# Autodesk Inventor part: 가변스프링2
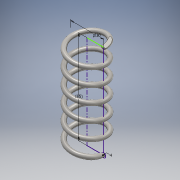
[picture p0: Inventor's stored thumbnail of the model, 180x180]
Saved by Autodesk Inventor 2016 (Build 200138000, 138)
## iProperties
Created: 2017-03
Part Number: 가변스프링2
Material: 강철, 탄소
Document SubType Name: Modeling
Designer: USER
Mass: 54.2866 g
Surface Area: 70.6255 cm^2
Volume: 6.91549 cm^3
Density: 7.85 g/cm^3
Appearance: 반연마
Author: USER
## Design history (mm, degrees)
sketch "스케치1"
  geometry: L1 (0, 0)-(-15, 0); L2 (-15, 0)-(-15, 31.632); L3 (-15, 31.632)-(0, 31.632); L4 (0, 31.632)-(0, 0); C1 r 2 at (-15, 0)
  constraints: 8 end point, 2 parallel, 1 centre point, 1 coincident, 1 horizontal, 1 perpendicular
  dimensions: "d0" = 4 diameter of C1; "d1" = 30 diameter of L2 L4; "d2" = 31.63241 distance between parallel lines of L1 L3 (derived)
feature "코일1" pitch "d3" = 10; turns "d5" = 6; dims "d4" = 31.63241 (= d2), "d6" = 0, angle "d7" = 90 deg, angle "d8" = 90 deg, "d9" = 0, "d10" = 0
sketch "스케치2"
  geometry: L1 (13, 0)-(17, 0) reference; 1 further point
  constraints: 1 horizontal alignment
extrude "돌출1" cut sketch "스케치2" stored distance "d11" = 10; taper "d12" = 0 deg
node "작업 평면1"
sketch "스케치3"
  geometry: L1 (-13, 0)-(-17, 0) reference; 1 further point
  constraints: 1 horizontal alignment
extrude "돌출2" cut sketch "스케치3" stored distance "d13" = 10; taper "d14" = 0 deg
node "솔리드1"
node "절단 모서리 투영1"
node "절단 모서리 투영2"
